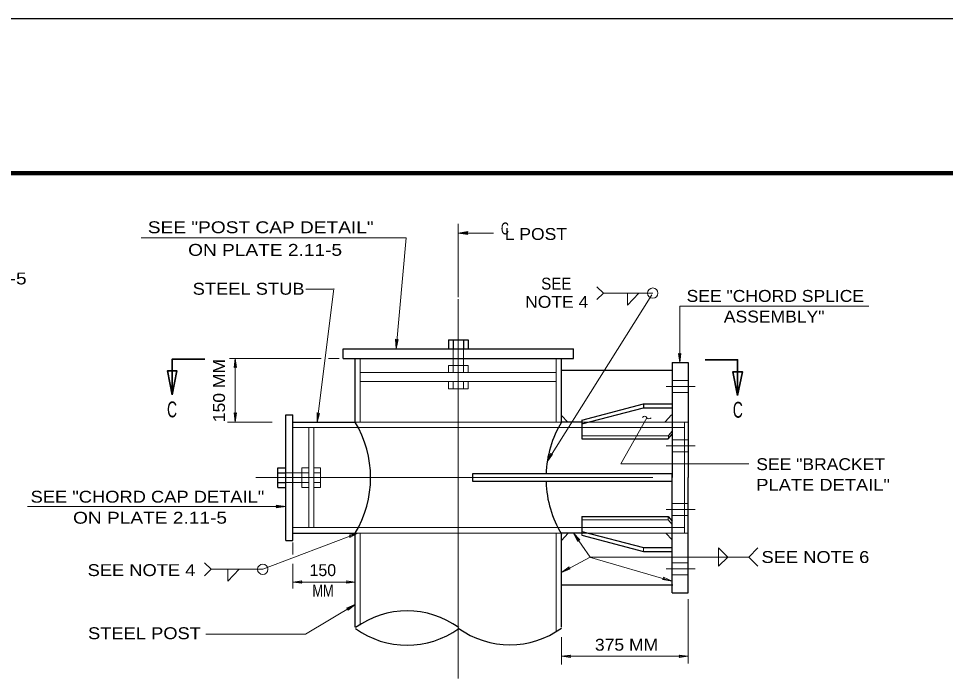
# Model space of a CAD drawing. Extents: x 312601.858 to 312602.699, y 144420.109 to 144420.704.
# Drawn here: x 312602.2309 to 312602.4645, y 144420.5372 to 144420.7035 of the extents above; entities that cross this region are included whole.
import ezdxf
from ezdxf.enums import TextEntityAlignment as Align

# ---------------------------------------------------------------- set-up
doc = ezdxf.new("R2010")
doc.units = 0
doc.header["$LTSCALE"] = 0.0012
for name, pattern in [('DOT_DASHED', [7.7, 5, -1.2, 0.3, -1.2]), ('LONG_DASHED', [7.5, 6, -1.5]), ('MEDIUM_DASHED', [4.5, 3, -1.5]), ('SHORT_DASHED', [2.7, 1.5, -1.2])]:
    doc.linetypes.add(name, pattern=pattern)
for name, color, linetype, lineweight in [('1', 7, 'Continuous', 13), ('2', 7, 'Continuous', 25), ('39', 7, 'Continuous', 13)]:
    doc.layers.add(name, color=color, linetype=linetype, lineweight=lineweight)

msp = doc.modelspace()

# ---------------------------------------------------------------- hatches: boundary and pattern name
at = {"layer": '39'}
for points in [[(312602.3439, 144420.6494), (312602.3441, 144420.6491), (312602.3417, 144420.6494), (312602.3441, 144420.6498)], [(312602.3262, 144420.6224), (312602.3265, 144420.6226), (312602.326, 144420.6203), (312602.3259, 144420.6227)], [(312602.3063, 144420.6039), (312602.3067, 144420.604), (312602.3061, 144420.6018), (312602.3061, 144420.6042)], [(312602.296, 144420.5805), (312602.2958, 144420.5809), (312602.2982, 144420.5805), (312602.2958, 144420.5802)]]:
    msp.add_hatch(color=256, dxfattribs=at).paths.add_polyline_path(points)

# ---------------------------------------------------------------- linework, layer by layer
at = {"layer": '1'}
for p, q in [((312602.3417, 144420.6518), (312602.3417, 144420.6333)), ((312602.3417, 144420.6494), (312602.3506, 144420.6494)), ((312602.2618, 144420.6482), (312602.3286, 144420.6482)), ((312602.3286, 144420.6482), (312602.326, 144420.6203)), ((312602.3033, 144420.6353), (312602.3101, 144420.6353)), ((312602.3103, 144420.6355), (312602.3061, 144420.6018)), ((312602.3766, 144420.6359), (312602.3783, 144420.6343)), ((312602.3766, 144420.6327), (312602.3783, 144420.6343)), ((312602.3783, 144420.6343), (312602.3907, 144420.6343)), ((312602.3843, 144420.6343), (312602.3843, 144420.6313)), ((312602.3872, 144420.6343), (312602.3843, 144420.6313)), ((312602.284, 144420.6178), (312602.3071, 144420.6178)), ((312602.2855, 144420.6178), (312602.2855, 144420.6018)), ((312602.309, 144420.6178), (312602.3117, 144420.6178)), ((312602.2835, 144420.6018), (312602.2948, 144420.6018)), ((312602.3827, 144420.5913), (312602.3892, 144420.6029)), ((312602.3827, 144420.5913), (312602.4149, 144420.5913)), ((312602.2331, 144420.5805), (312602.2982, 144420.5805)), ((312602.2924, 144420.5647), (312602.3164, 144420.5738)), ((312602.3749, 144420.5678), (312602.3707, 144420.5738)), ((312602.3, 144420.5723), (312602.3, 144420.5727)), ((312602.3, 144420.5684), (312602.3, 144420.5715)), ((312602.3884, 144420.5691), (312602.3884, 144420.5703)), ((312602.4073, 144420.5701), (312602.4096, 144420.5678)), ((312602.4073, 144420.5655), (312602.4073, 144420.5701)), ((312602.4149, 144420.5678), (312602.4172, 144420.5701)), ((312602.3749, 144420.5678), (312602.3677, 144420.5639)), ((312602.3955, 144420.5617), (312602.3748, 144420.5678)), ((312602.3749, 144420.5678), (312602.4149, 144420.5678)), ((312602.4073, 144420.5655), (312602.4096, 144420.5678)), ((312602.4149, 144420.5678), (312602.4172, 144420.5655)), ((312602.2794, 144420.5647), (312602.2924, 144420.5647)), ((312602.3, 144420.5599), (312602.3, 144420.5661)), ((312602.3, 144420.5615), (312602.3157, 144420.5615)), ((312602.3996, 144420.541), (312602.3996, 144420.5572)), ((312602.3032, 144420.5484), (312602.3157, 144420.5558)), ((312602.2781, 144420.5484), (312602.3032, 144420.5484)), ((312602.3677, 144420.5407), (312602.3677, 144420.5476)), ((312602.3677, 144420.5428), (312602.3996, 144420.5428))]:
    msp.add_line(p, q, dxfattribs=at)
at = {"layer": '1', "linetype": 'DOT_DASHED'}
for p, q in [((312602.3417, 144420.6328), (312602.3417, 144420.5372)), ((312602.3941, 144420.6108), (312602.4014, 144420.6108)), ((312602.3941, 144420.5958), (312602.4014, 144420.5958)), ((312602.2907, 144420.5878), (312602.4067, 144420.5878)), ((312602.3941, 144420.5798), (312602.4014, 144420.5798)), ((312602.3941, 144420.5648), (312602.4014, 144420.5648))]:
    msp.add_line(p, q, dxfattribs=at)
at = {"layer": '1', "lineweight": 25}
for p, q in [((312602.3127, 144420.6203), (312602.3707, 144420.6203)), ((312602.3127, 144420.6178), (312602.3127, 144420.6203)), ((312602.3392, 144420.6225), (312602.3442, 144420.6225)), ((312602.3392, 144420.6225), (312602.3392, 144420.6203)), ((312602.3404, 144420.6225), (312602.3404, 144420.6202)), ((312602.343, 144420.6225), (312602.343, 144420.6202)), ((312602.3442, 144420.6225), (312602.3442, 144420.6203)), ((312602.3707, 144420.6178), (312602.3707, 144420.6203)), ((312602.3127, 144420.6178), (312602.3707, 144420.6178)), ((312602.3677, 144420.6018), (312602.3677, 144420.6178)), ((312602.3956, 144420.6168), (312602.3956, 144420.5878)), ((312602.3956, 144420.6168), (312602.3996, 144420.6168)), ((312602.3996, 144420.6168), (312602.3996, 144420.5878)), ((312602.3958, 144420.6148), (312602.3677, 144420.6148)), ((312602.3728, 144420.6023), (312602.3884, 144420.6064)), ((312602.3884, 144420.6064), (312602.3956, 144420.6064)), ((312602.3884, 144420.6064), (312602.3884, 144420.6054)), ((312602.2982, 144420.572), (312602.2982, 144420.6036)), ((312602.2982, 144420.6036), (312602.3, 144420.6036)), ((312602.3, 144420.572), (312602.3, 144420.6036)), ((312602.3693, 144420.6018), (312602.3677, 144420.6035)), ((312602.3728, 144420.6018), (312602.3677, 144420.6018)), ((312602.3728, 144420.6023), (312602.3728, 144420.5976)), ((312602.3728, 144420.5976), (312602.3946, 144420.5976)), ((312602.3946, 144420.5976), (312602.3956, 144420.5988)), ((312602.2962, 144420.5853), (312602.2962, 144420.5903)), ((312602.2962, 144420.5903), (312602.2982, 144420.5903)), ((312602.2962, 144420.589), (312602.2982, 144420.589)), ((312602.3956, 144420.5588), (312602.3956, 144420.5878)), ((312602.3996, 144420.5588), (312602.3996, 144420.5878)), ((312602.2962, 144420.5866), (312602.2982, 144420.5866)), ((312602.2962, 144420.5853), (312602.2982, 144420.5853)), ((312602.3728, 144420.578), (312602.3728, 144420.5736)), ((312602.3728, 144420.578), (312602.3946, 144420.578)), ((312602.3946, 144420.578), (312602.3956, 144420.5768)), ((312602.3, 144420.5738), (312602.3157, 144420.5738)), ((312602.3157, 144420.5501), (312602.3157, 144420.5738)), ((312602.3677, 144420.5501), (312602.3677, 144420.5738)), ((312602.3728, 144420.5738), (312602.3677, 144420.5738)), ((312602.3677, 144420.572), (312602.3694, 144420.5738)), ((312602.2982, 144420.572), (312602.3, 144420.572)), ((312602.3728, 144420.5733), (312602.3884, 144420.5692)), ((312602.3884, 144420.5692), (312602.3956, 144420.5692)), ((312602.3958, 144420.5607), (312602.3677, 144420.5607)), ((312602.3956, 144420.5588), (312602.3996, 144420.5588))]:
    msp.add_line(p, q, dxfattribs=at)
at = {"layer": '1', "linetype": 'MEDIUM_DASHED'}
for p, q in [((312602.3404, 144420.6203), (312602.3404, 144420.6143)), ((312602.343, 144420.6203), (312602.343, 144420.6143)), ((312602.3392, 144420.6161), (312602.3442, 144420.6161)), ((312602.3392, 144420.6161), (312602.3392, 144420.6143)), ((312602.3442, 144420.6161), (312602.3442, 144420.6143)), ((312602.3392, 144420.612), (312602.3392, 144420.6102)), ((312602.3404, 144420.612), (312602.3404, 144420.6102)), ((312602.343, 144420.612), (312602.343, 144420.6102)), ((312602.3442, 144420.612), (312602.3442, 144420.6102)), ((312602.3392, 144420.6102), (312602.3442, 144420.6102)), ((312602.3023, 144420.5903), (312602.3023, 144420.5853)), ((312602.3023, 144420.5903), (312602.304, 144420.5903)), ((312602.3053, 144420.5903), (312602.307, 144420.5903)), ((312602.307, 144420.5903), (312602.307, 144420.5853)), ((312602.2982, 144420.589), (312602.304, 144420.589)), ((312602.3053, 144420.589), (312602.307, 144420.589)), ((312602.2982, 144420.5866), (312602.304, 144420.5866)), ((312602.3023, 144420.5853), (312602.304, 144420.5853)), ((312602.3053, 144420.5866), (312602.307, 144420.5866)), ((312602.3053, 144420.5853), (312602.307, 144420.5853))]:
    msp.add_line(p, q, dxfattribs=at)
at = {"layer": '1', "linetype": 'LONG_DASHED'}
for p, q in [((312602.317, 144420.6018), (312602.317, 144420.6178)), ((312602.3664, 144420.6018), (312602.3664, 144420.6178)), ((312602.317, 144420.6143), (312602.3664, 144420.6143)), ((312602.317, 144420.612), (312602.3664, 144420.612)), ((312602.3158, 144420.6018), (312602.3417, 144420.6018)), ((312602.3677, 144420.6018), (312602.3417, 144420.6018)), ((312602.3996, 144420.6018), (312602.3729, 144420.6018)), ((312602.3954, 144420.6036), (312602.3938, 144420.6019)), ((312602.3987, 144420.6018), (312602.3987, 144420.5878)), ((312602.3, 144420.6004), (312602.3985, 144420.6004)), ((312602.304, 144420.6004), (312602.304, 144420.5752)), ((312602.3053, 144420.6004), (312602.3053, 144420.5752)), ((312602.3947, 144420.5984), (312602.3956, 144420.5995)), ((312602.3946, 144420.5983), (312602.3731, 144420.5983)), ((312602.3947, 144420.5976), (312602.3947, 144420.5983)), ((312602.3987, 144420.5738), (312602.3987, 144420.5878)), ((312602.3728, 144420.5733), (312602.3728, 144420.578)), ((312602.3944, 144420.5772), (312602.3729, 144420.5772)), ((312602.3946, 144420.5772), (312602.3946, 144420.5779)), ((312602.3946, 144420.5772), (312602.3956, 144420.576)), ((312602.3946, 144420.5772), (312602.3956, 144420.576)), ((312602.3, 144420.5752), (312602.3985, 144420.5752)), ((312602.3158, 144420.5738), (312602.3417, 144420.5738)), ((312602.317, 144420.5506), (312602.317, 144420.5738)), ((312602.3676, 144420.5738), (312602.3417, 144420.5738)), ((312602.3664, 144420.5491), (312602.3664, 144420.5738)), ((312602.3995, 144420.5738), (312602.373, 144420.5738)), ((312602.3956, 144420.5721), (312602.394, 144420.5738))]:
    msp.add_line(p, q, dxfattribs=at)
at = {"layer": '1', "linetype": 'SHORT_DASHED'}
for p, q in [((312602.3956, 144420.6123), (312602.3996, 144420.6123)), ((312602.3956, 144420.6093), (312602.3996, 144420.6093)), ((312602.3956, 144420.5973), (312602.3996, 144420.5973)), ((312602.3956, 144420.5943), (312602.3996, 144420.5943)), ((312602.3956, 144420.5813), (312602.3996, 144420.5813)), ((312602.3956, 144420.5783), (312602.3996, 144420.5783)), ((312602.3956, 144420.5663), (312602.3996, 144420.5663)), ((312602.3956, 144420.5633), (312602.3996, 144420.5633))]:
    msp.add_line(p, q, dxfattribs=at)
at = {"layer": '1'}
msp.add_lwpolyline([(312602.3975, 144420.6168), (312602.3975, 144420.631), (312602.4452, 144420.631)], dxfattribs=at)
for points in [[(312602.3978, 144420.6191), (312602.3975, 144420.6168), (312602.3972, 144420.6191), (312602.3975, 144420.6188)], [(312602.2852, 144420.6156), (312602.2855, 144420.6178), (312602.2858, 144420.6156), (312602.2855, 144420.6158)], [(312602.2858, 144420.6041), (312602.2855, 144420.6018), (312602.2852, 144420.6041), (312602.2855, 144420.6038)], [(312602.3654, 144420.5937), (312602.3641, 144420.5918), (312602.3649, 144420.5939), (312602.3651, 144420.5936)], [(312602.3142, 144420.5733), (312602.3164, 144420.5738), (312602.3144, 144420.5727), (312602.3145, 144420.5731)], [(312602.3718, 144420.5717), (312602.3707, 144420.5738), (312602.3723, 144420.5721), (312602.3719, 144420.5721)], [(312602.3699, 144420.5648), (312602.3677, 144420.5639), (312602.3696, 144420.5653), (312602.3695, 144420.5649)], [(312602.3023, 144420.5612), (312602.3, 144420.5615), (312602.3023, 144420.5618), (312602.302, 144420.5615)], [(312602.3135, 144420.5618), (312602.3157, 144420.5615), (312602.3135, 144420.5612), (312602.3137, 144420.5615)], [(312602.3934, 144420.5627), (312602.3956, 144420.5617), (312602.3932, 144420.5621), (312602.3936, 144420.5623)], [(312602.37, 144420.5425), (312602.3677, 144420.5428), (312602.37, 144420.5431), (312602.3697, 144420.5428)], [(312602.3974, 144420.5431), (312602.3996, 144420.5428), (312602.3974, 144420.5425), (312602.3976, 144420.5428)]]:
    msp.add_lwpolyline(points, close=True, dxfattribs=at)
at = {"layer": '1', "lineweight": 25}
for points in [[(312602.3, 144420.6018), (312602.3157, 144420.6018), (312602.3157, 144420.6178)], [(312602.3728, 144420.6014), (312602.3884, 144420.6054), (312602.3956, 144420.6054)], [(312602.3728, 144420.5742), (312602.3884, 144420.5702), (312602.3956, 144420.5702)]]:
    msp.add_lwpolyline(points, dxfattribs=at)
msp.add_lwpolyline([(312602.3453, 144420.5869), (312602.3956, 144420.5869), (312602.3956, 144420.5888), (312602.3453, 144420.5888)], close=True, dxfattribs=at)
at = {"layer": '1'}
for centre in [(312602.3907, 144420.6343), (312602.2924, 144420.5647)]:
    msp.add_circle(centre, 0.0013, dxfattribs=at)
at = {"layer": '1', "lineweight": 25}
for centre, start, end in [((312602.292523, 144420.5878), 328.86596, 31.13404), ((312602.390877, 144420.5878), 148.86596, 178.1207), ((312602.390877, 144420.5876), 181.8793, 211.13404)]:
    msp.add_arc(centre, 0.0270771, start, end, dxfattribs=at)
at = {"layer": '1'}
for centre, radius, start, end in [((312602.388627, 144420.602696), 0.0006083, 19.58072, 150.03043), ((312602.38975, 144420.60325), 0.0006519, 212.47119, 327.52881)]:
    msp.add_arc(centre, radius, start, end, dxfattribs=at)
at = {"layer": '2', "lineweight": 13}
msp.add_line((312602.3641, 144420.5919), (312602.3905, 144420.6339), dxfattribs=at)
for points in [[(312602.2777, 144420.5631), (312602.2794, 144420.5647), (312602.2777, 144420.5663)], [(312602.2836, 144420.5647), (312602.2836, 144420.5617), (312602.2865, 144420.5647)]]:
    msp.add_lwpolyline(points, dxfattribs=at)
at = {"layer": '2'}
msp.add_lwpolyline([(312602.3136, 144420.5549), (312602.3157, 144420.5558), (312602.3139, 144420.5544), (312602.3139, 144420.5548)], close=True, dxfattribs=at)
for centre, start, end in [((312602.3288, 144420.532057), 54.07583, 125.92417), ((312602.3288, 144420.567743), 234.07583, 305.92417), ((312602.3547, 144420.567843), 234.07583, 305.92417)]:
    msp.add_arc(centre, 0.0221573, start, end, dxfattribs=at)
at = {"layer": '39', "lineweight": 25}
msp.add_line((312601.8578, 144420.7035), (312602.6988, 144420.7035), dxfattribs=at)
at = {"layer": '39', "lineweight": 158}
msp.add_line((312601.9088, 144420.6645), (312602.6838, 144420.6645), dxfattribs=at)
at = {"layer": '39'}
for points in [[(312602.3439, 144420.6494), (312602.3441, 144420.6491), (312602.3417, 144420.6494), (312602.3441, 144420.6498)], [(312602.3262, 144420.6224), (312602.3265, 144420.6226), (312602.326, 144420.6203), (312602.3259, 144420.6227)], [(312602.2708, 144420.6147), (312602.2696, 144420.6087), (312602.2684, 144420.6147)], [(312602.4109, 144420.6145), (312602.4121, 144420.6085), (312602.4133, 144420.6145)], [(312602.3063, 144420.6039), (312602.3067, 144420.604), (312602.3061, 144420.6018), (312602.3061, 144420.6042)], [(312602.296, 144420.5805), (312602.2958, 144420.5809), (312602.2982, 144420.5805), (312602.2958, 144420.5802)]]:
    msp.add_lwpolyline(points, close=True, dxfattribs=at)
at = {"layer": '39', "lineweight": 35}
for points in [[(312602.2696, 144420.609), (312602.2696, 144420.6177), (312602.2778, 144420.6177)], [(312602.4121, 144420.6088), (312602.4121, 144420.6175), (312602.4039, 144420.6175)]]:
    msp.add_lwpolyline(points, dxfattribs=at)
for points in [[(312602.2696, 144420.6087), (312602.2684, 144420.6147), (312602.2708, 144420.6147)], [(312602.4121, 144420.6085), (312602.4133, 144420.6145), (312602.4109, 144420.6145)]]:
    msp.add_lwpolyline(points, close=True, dxfattribs=at)

# ---------------------------------------------------------------- texts
at = {"layer": '2'}
for s, height, width, p in [('SEE "POST CAP DETAIL"', 0.003, 1.2, (312602.2919, 144420.6494)), ('C', 0.003, 0.7, (312602.35345, 144420.6491)), ('L POST', 0.003, 1.1, (312602.36125, 144420.6477)), ('ON PLATE 2.11-5', 0.003, 1.2, (312602.293, 144420.6437)), ('ON PLATE 2.11-5', 0.003, 1.2, (312602.2135, 144420.6365)), ('STEEL STUB', 0.003, 1.15, (312602.28885, 144420.6339)), ('SEE', 0.003, 0.95, (312602.3664, 144420.6352)), ('SEE "CHORD SPLICE', 0.003, 1.1, (312602.4216, 144420.6321)), ('NOTE 4', 0.003, 1.1, (312602.3665, 144420.6306)), ('ASSEMBLY"', 0.003, 1.1, (312602.4213, 144420.6269)), ('C', 0.004, 0.65, (312602.26955, 144420.603)), ('C', 0.004, 0.65, (312602.41215, 144420.6029)), ('SEE "CHORD CAP DETAIL"', 0.003, 1.15, (312602.26335, 144420.5815)), ('ON PLATE 2.11-5', 0.003, 1.2, (312602.264, 144420.5762)), ('SEE NOTE 6', 0.003, 1.15, (312602.4317, 144420.5663)), ('SEE NOTE 4', 0.003, 1.15, (312602.26185, 144420.563)), ('MM', 0.003, 0.8, (312602.3076, 144420.5578)), ('STEEL POST', 0.003, 1.15, (312602.2626, 144420.5471)), ('375 MM', 0.003, 1.1, (312602.3841, 144420.5442))]:
    msp.add_text(s, height=height, dxfattribs=dict(at, width=width)).set_placement(p, align=Align.CENTER)
at = {"layer": '2', "width": 1.1}
msp.add_text('150 MM', height=0.003, rotation=90, dxfattribs=at).set_placement((312602.2829, 144420.60975), align=Align.CENTER)
at = {"layer": '2'}
for s, width, p in [('SEE "BRACKET', 1.1, (312602.4168, 144420.5897)), ('PLATE DETAIL"', 1.15, (312602.4168, 144420.5845))]:
    msp.add_text(s, height=0.003, dxfattribs=dict(at, width=width)).set_placement(p)
msp.add_text('150', height=0.003, dxfattribs=at).set_placement((312602.30755, 144420.563), align=Align.CENTER)

doc.saveas('drawing.dxf')
